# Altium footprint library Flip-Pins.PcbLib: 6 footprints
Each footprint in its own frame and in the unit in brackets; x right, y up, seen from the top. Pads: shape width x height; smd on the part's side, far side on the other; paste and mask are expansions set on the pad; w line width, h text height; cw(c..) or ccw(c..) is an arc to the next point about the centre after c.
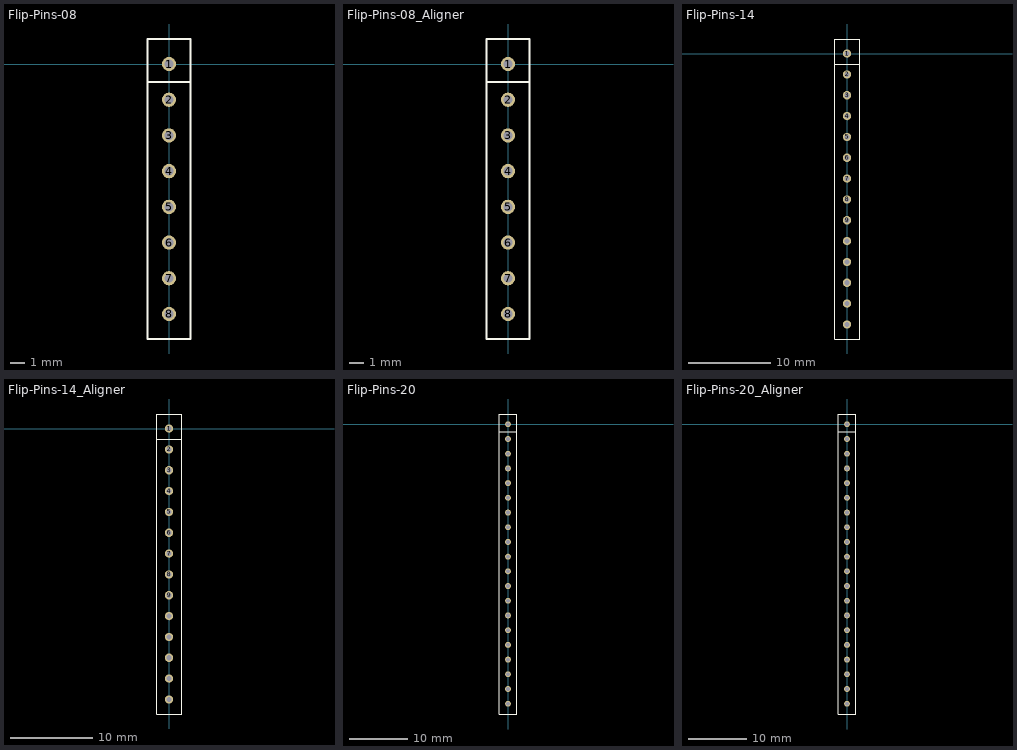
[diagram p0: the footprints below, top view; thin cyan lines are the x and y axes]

## Flip-Pins-08 [mil] "Flip-Pins 8 pins"
height 250
pads (8):
  round 40 hole 25: 1(0,0) 2(0,-100) 3(0,-200) 4(0,-300) 5(0,-400) 6(0,-500) 7(0,-600) 8(0,-700)
Top Overlay:
  lines w6: -60,-50 60,-50 ; -60,-770 -60,70 60,70 60,-770 -60,-770
Bottom Overlay:
  lines w6: -60,-50 60,-50 ; -60,-770 -60,70 60,70 60,-770 -60,-770
3D body: height 239.97, standoff -61.21, extent -7.88,-740 7.88,39.92

## Flip-Pins-08_Aligner [mil] "Flip-Pins 8 pins with Aligner"
height 250
pads (8):
  round 40 hole 25: 1(0,0) 2(0,-100) 3(0,-200) 4(0,-300) 5(0,-400) 6(0,-500) 7(0,-600) 8(0,-700)
Top Overlay:
  lines w6: -60,-50 60,-50 ; -60,-770 -60,70 60,70 60,-770 -60,-770
Bottom Overlay:
  lines w6: -60,-50 60,-50 ; -60,-770 -60,70 60,70 60,-770 -60,-770
3D body: height 239.97, standoff -61.21, extent -47,-59.84 47.49,59.84
3D body: height 239.97, standoff -61.21, extent -47,-159.84 47.49,-40.16
3D body: height 239.97, standoff -61.21, extent -47,-259.84 47.49,-140.16
3D body: height 239.97, standoff -61.21, extent -47,-359.84 47.49,-240.16
3D body: height 239.97, standoff -61.21, extent -47,-459.84 47.49,-340.16
3D body: height 239.97, standoff -61.21, extent -47,-559.84 47.49,-440.16
3D body: height 239.97, standoff -61.21, extent -47,-659.84 47.49,-540.16
3D body: height 239.97, standoff -61.21, extent -47,-759.84 47.49,-640.16

## Flip-Pins-14 [mil] "Flip-Pins 14 pins"
height 250
pads (14):
  round 40 hole 25: 1(0,0) 2(0,-100) 3(0,-200) 4(0,-300) 5(0,-400) 6(0,-500) 7(0,-600) 8(0,-700) 9(0,-800) 10(0,-900) 11(0,-1000) 12(0,-1100) 13(0,-1200) 14(0,-1300)
Top Overlay:
  lines w6: -60,-50 60,-50 ; -60,-1370 60,-1370 60,70 -60,70 -60,-1370
Bottom Overlay:
  lines w6: -60,-50 60,-50 ; -60,-1370 60,-1370 60,70 -60,70 -60,-1370
3D body: height 239.97, standoff -61.21, extent -7.88,-1340 7.88,39.92

## Flip-Pins-14_Aligner [mil] "Flip-Pins 14 pins with Aligner"
height 250
pads (14):
  round 40 hole 25: 1(0,0) 2(0,-100) 3(0,-200) 4(0,-300) 5(0,-400) 6(0,-500) 7(0,-600) 8(0,-700) 9(0,-800) 10(0,-900) 11(0,-1000) 12(0,-1100) 13(0,-1200) 14(0,-1300)
Top Overlay:
  lines w6: -60,-50 60,-50 ; -60,-1370 60,-1370 60,70 -60,70 -60,-1370
Bottom Overlay:
  lines w6: -60,-50 60,-50 ; -60,-1370 60,-1370 60,70 -60,70 -60,-1370
3D body: height 239.97, standoff -61.21, extent -47,-59.84 47.49,59.84
3D body: height 239.97, standoff -61.21, extent -47,-159.84 47.49,-40.16
3D body: height 239.97, standoff -61.21, extent -47,-259.84 47.49,-140.16
3D body: height 239.97, standoff -61.21, extent -47,-359.84 47.49,-240.16
3D body: height 239.97, standoff -61.21, extent -47,-459.84 47.49,-340.16
3D body: height 239.97, standoff -61.21, extent -47,-559.84 47.49,-440.16
3D body: height 239.97, standoff -61.21, extent -47,-659.84 47.49,-540.16
3D body: height 239.97, standoff -61.21, extent -47,-759.84 47.49,-640.16
3D body: height 239.97, standoff -61.21, extent -47,-859.84 47.49,-740.16
3D body: height 239.97, standoff -61.21, extent -47,-959.84 47.49,-840.16
3D body: height 239.97, standoff -61.21, extent -47,-1059.84 47.49,-940.16
3D body: height 239.97, standoff -61.21, extent -47,-1159.84 47.49,-1040.16
3D body: height 239.97, standoff -61.21, extent -47,-1259.84 47.49,-1140.16
3D body: height 239.97, standoff -61.21, extent -47,-1359.84 47.49,-1240.16

## Flip-Pins-20 [mil] "Flip-Pins 20 pins"
height 250
pads (20):
  round 40 hole 25: 1(0,0) 2(0,-100) 3(0,-200) 4(0,-300) 5(0,-400) 6(0,-500) 7(0,-600) 8(0,-700) 9(0,-800) 10(0,-900) 11(0,-1000) 12(0,-1100) 13(0,-1200) 14(0,-1300) 15(0,-1400) 16(0,-1500) 17(0,-1600) 18(0,-1700) 19(0,-1800) 20(0,-1900)
Top Overlay:
  lines w6: -60,-50 60,-50 ; -60,-1970 60,-1970 60,70 -60,70 -60,-1970
Bottom Overlay:
  lines w6: -60,-50 60,-50 ; -60,-1970 60,-1970 60,70 -60,70 -60,-1970
3D body: height 240, standoff -61.18, extent -7.88,-1939.96 7.87,-1860.04
3D body: height 240, standoff -61.18, extent -7.88,-1839.96 7.87,-1760.04
3D body: height 240, standoff -61.18, extent -7.88,-1739.96 7.87,-1660.04
3D body: height 240, standoff -61.18, extent -7.88,-1639.96 7.87,-1560.04
3D body: height 240, standoff -61.18, extent -7.88,-1539.96 7.87,-1460.04
3D body: height 240, standoff -61.18, extent -7.88,-1439.96 7.87,-1360.04
3D body: height 239.97, standoff -61.21, extent -7.88,-1340 7.88,39.92

## Flip-Pins-20_Aligner [mil] "Flip-Pins 20 pins with Aligner"
height 250
pads (20):
  round 40 hole 25: 1(0,0) 2(0,-100) 3(0,-200) 4(0,-300) 5(0,-400) 6(0,-500) 7(0,-600) 8(0,-700) 9(0,-800) 10(0,-900) 11(0,-1000) 12(0,-1100) 13(0,-1200) 14(0,-1300) 15(0,-1400) 16(0,-1500) 17(0,-1600) 18(0,-1700) 19(0,-1800) 20(0,-1900)
Top Overlay:
  lines w6: -60,-50 60,-50 ; -60,-1970 -60,70 60,70 60,-1970 -60,-1970
Bottom Overlay:
  lines w6: -60,-50 60,-50 ; -60,-1970 -60,70 60,70 60,-1970 -60,-1970
3D body: height 239.97, standoff -61.21, extent -47,-1959.84 47.49,-1840.16
3D body: height 239.97, standoff -61.21, extent -47,-1859.84 47.49,-1740.16
3D body: height 239.97, standoff -61.21, extent -47,-1759.84 47.49,-1640.16
3D body: height 239.97, standoff -61.21, extent -47,-1659.84 47.49,-1540.16
3D body: height 239.97, standoff -61.21, extent -47,-1559.84 47.49,-1440.16
3D body: height 239.97, standoff -61.21, extent -47,-1459.84 47.49,-1340.16
3D body: height 239.97, standoff -61.21, extent -47,-1359.84 47.49,-1240.16
3D body: height 239.97, standoff -61.21, extent -47,-1259.84 47.49,-1140.16
3D body: height 239.97, standoff -61.21, extent -47,-1159.84 47.49,-1040.16
3D body: height 239.97, standoff -61.21, extent -47,-1059.84 47.49,-940.16
3D body: height 239.97, standoff -61.21, extent -47,-959.84 47.49,-840.16
3D body: height 239.97, standoff -61.21, extent -47,-859.84 47.49,-740.16
3D body: height 239.97, standoff -61.21, extent -47,-759.84 47.49,-640.16
3D body: height 239.97, standoff -61.21, extent -47,-659.84 47.49,-540.16
3D body: height 239.97, standoff -61.21, extent -47,-559.84 47.49,-440.16
3D body: height 239.97, standoff -61.21, extent -47,-459.84 47.49,-340.16
3D body: height 239.97, standoff -61.21, extent -47,-359.84 47.49,-240.16
3D body: height 239.97, standoff -61.21, extent -47,-259.84 47.49,-140.16
3D body: height 239.97, standoff -61.21, extent -47,-159.84 47.49,-40.16
3D body: height 239.97, standoff -61.21, extent -47,-59.84 47.49,59.84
